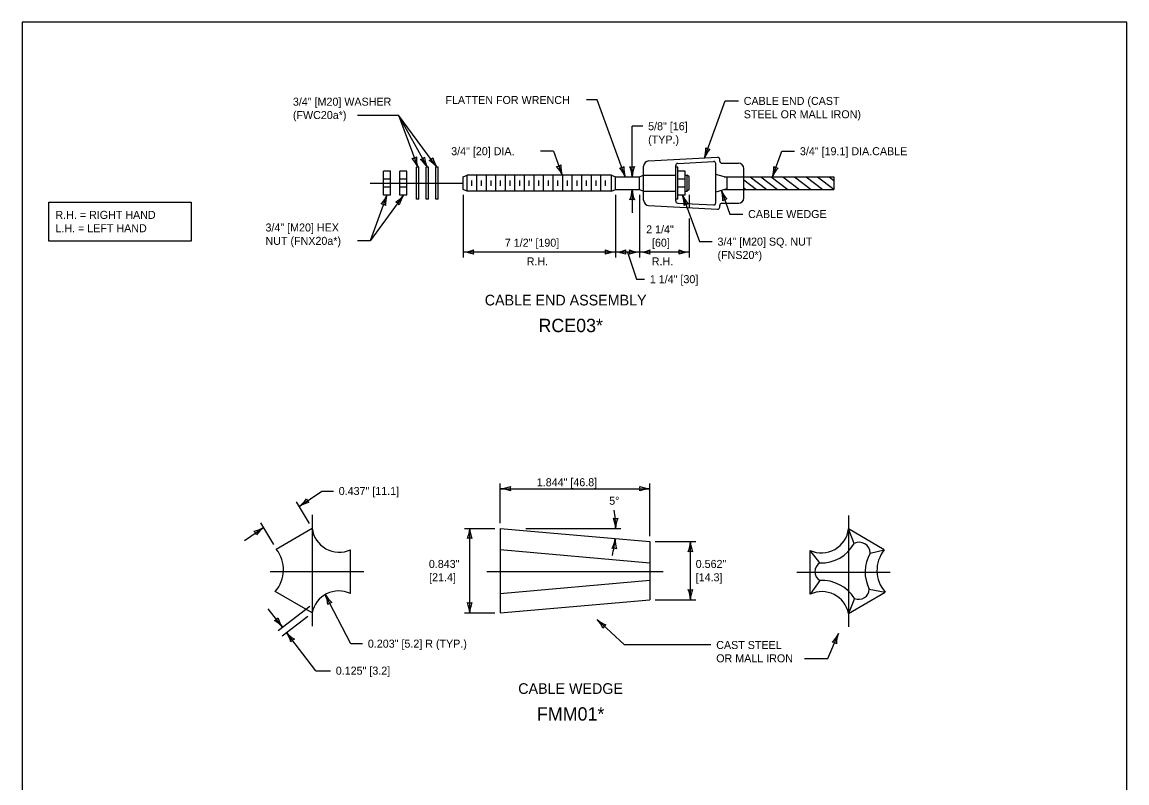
# Model space of a CAD drawing. Extents: x 49991.4 to 50021, y 49987.6 to 50011.4.
# Drawn here: x 50000.34 to 50008.61, y 50005.56 to 50011.26 of the extents above; entities that cross this region are included whole.
import ezdxf

# ---------------------------------------------------------------- set-up
doc = ezdxf.new("R2010")
doc.units = 0
for name, color, linetype in [('Level 1', 7, 'Continuous'), ('Level 2', 7, 'Continuous'), ('Level 3', 7, 'Continuous'), ('Level 4', 7, 'Continuous'), ('Level 5', 7, 'Continuous')]:
    doc.layers.add(name, color=color, linetype=linetype)

msp = doc.modelspace()

# ---------------------------------------------------------------- linework, layer by layer
at = {"layer": 'Level 1'}
for p, q in [((50005.0307, 50010.2226), (50005.5471, 50010.2498)), ((50005.2487, 50010.2041), (50005.5171, 50010.2182)), ((50005.5637, 50010.2215), (50005.5637, 50010.2341)), ((50003.0429, 50009.9656), (50003.0429, 50010.1456)), ((50003.0954, 50010.1456), (50003.0429, 50010.1456)), ((50003.0954, 50009.9656), (50003.0954, 50010.1456)), ((50003.1674, 50009.9656), (50003.1674, 50010.1456)), ((50003.2199, 50010.1456), (50003.1674, 50010.1456)), ((50003.2199, 50009.9656), (50003.2199, 50010.1456)), ((50003.3087, 50010.1756), (50003.2919, 50010.1756)), ((50003.2919, 50009.9356), (50003.2919, 50010.1756)), ((50003.3087, 50009.9356), (50003.3087, 50010.1756)), ((50003.3807, 50010.1756), (50003.3639, 50010.1756)), ((50003.3639, 50009.9356), (50003.3639, 50010.1756)), ((50003.3807, 50009.9356), (50003.3807, 50010.1756)), ((50003.4527, 50010.1756), (50003.4359, 50010.1756)), ((50003.4359, 50009.9356), (50003.4359, 50010.1756)), ((50003.4527, 50009.9356), (50003.4527, 50010.1756)), ((50004.9933, 50009.9279), (50004.9933, 50010.1832)), ((50005.2338, 50009.9228), (50005.2338, 50010.1883)), ((50005.2506, 50010.1756), (50005.2338, 50010.1756)), ((50005.2506, 50009.9356), (50005.2506, 50010.1756)), ((50005.3046, 50010.1456), (50005.2506, 50010.1456)), ((50005.3046, 50009.9656), (50005.3046, 50010.1456)), ((50005.5337, 50009.9087), (50005.5337, 50010.2024)), ((50005.5795, 50010.2057), (50005.7044, 50010.2057)), ((50005.7439, 50009.9449), (50005.7439, 50010.1662)), ((50003.0954, 50010.0856), (50003.0429, 50010.0856)), ((50003.2199, 50010.0856), (50003.1674, 50010.0856)), ((50003.6414, 50010.1036), (50003.6714, 50010.1156)), ((50003.6414, 50010.0075), (50003.6414, 50010.1036)), ((50003.6714, 50009.9956), (50003.6714, 50010.1156)), ((50004.7522, 50010.1156), (50003.6714, 50010.1156)), ((50003.7069, 50010.0369), (50003.7069, 50010.0763)), ((50003.7429, 50009.9956), (50003.7429, 50010.1156)), ((50003.7784, 50010.0369), (50003.7784, 50010.0763)), ((50003.8145, 50009.9956), (50003.8145, 50010.1156)), ((50003.85, 50010.0369), (50003.85, 50010.0763)), ((50003.886, 50009.9956), (50003.886, 50010.1156)), ((50003.9215, 50010.0369), (50003.9215, 50010.0763)), ((50003.9576, 50009.9956), (50003.9576, 50010.1156)), ((50003.9931, 50010.0369), (50003.9931, 50010.0763)), ((50004.0291, 50009.9956), (50004.0291, 50010.1156)), ((50004.0646, 50010.0369), (50004.0646, 50010.0763)), ((50004.1007, 50009.9956), (50004.1007, 50010.1156)), ((50004.1362, 50010.0369), (50004.1362, 50010.0763)), ((50004.1722, 50009.9956), (50004.1722, 50010.1156)), ((50004.2077, 50010.0369), (50004.2077, 50010.0763)), ((50004.2437, 50009.9956), (50004.2437, 50010.1156)), ((50004.2792, 50010.0369), (50004.2792, 50010.0763)), ((50004.3153, 50009.9956), (50004.3153, 50010.1156)), ((50004.3508, 50010.0369), (50004.3508, 50010.0763)), ((50004.3868, 50009.9956), (50004.3868, 50010.1156)), ((50004.4223, 50010.0369), (50004.4223, 50010.0763)), ((50004.4584, 50009.9956), (50004.4584, 50010.1156)), ((50004.4939, 50010.0369), (50004.4939, 50010.0763)), ((50004.5299, 50009.9956), (50004.5299, 50010.1156)), ((50004.5654, 50010.0369), (50004.5654, 50010.0763)), ((50004.6015, 50009.9956), (50004.6015, 50010.1156)), ((50004.637, 50010.0369), (50004.637, 50010.0763)), ((50004.673, 50009.9956), (50004.673, 50010.1156)), ((50004.7085, 50010.0369), (50004.7085, 50010.0763)), ((50004.7522, 50009.9956), (50004.7522, 50010.1156)), ((50004.7522, 50010.1156), (50004.7822, 50010.1036)), ((50004.7822, 50010.1036), (50004.9633, 50010.1036)), ((50004.7822, 50010.0075), (50004.7822, 50010.1036)), ((50004.9633, 50010.1036), (50004.9933, 50010.1156)), ((50004.9633, 50010.0075), (50004.9633, 50010.1036)), ((50005.3046, 50010.0856), (50005.2506, 50010.0856)), ((50005.3046, 50010.1156), (50005.3196, 50010.1156)), ((50005.3196, 50009.9956), (50005.3196, 50010.1156)), ((50005.3346, 50010.1036), (50005.3196, 50010.1156)), ((50005.3346, 50010.0075), (50005.3346, 50010.1036)), ((50005.7439, 50010.1033), (50006.418, 50010.1033)), ((50005.7439, 50010.0803), (50005.8386, 50010.0079)), ((50005.792, 50010.1033), (50005.9172, 50010.0079)), ((50005.871, 50010.1033), (50005.996, 50010.0079)), ((50005.9492, 50010.1033), (50006.0744, 50010.0079)), ((50006.0364, 50010.1033), (50006.1614, 50010.0079)), ((50006.1242, 50010.1033), (50006.2492, 50010.0079)), ((50006.212, 50010.1033), (50006.3372, 50010.0079)), ((50006.2972, 50010.1033), (50006.418, 50010.0111)), ((50006.3824, 50010.1033), (50006.418, 50010.0761)), ((50006.418, 50010.1033), (50006.418, 50010.0079)), ((50003.0954, 50010.0256), (50003.0429, 50010.0256)), ((50003.0954, 50009.9656), (50003.0429, 50009.9656)), ((50003.2199, 50010.0256), (50003.1674, 50010.0256)), ((50003.2199, 50009.9656), (50003.1674, 50009.9656)), ((50003.6714, 50009.9956), (50003.6414, 50010.0075)), ((50004.7522, 50009.9956), (50003.6714, 50009.9956)), ((50004.7522, 50009.9956), (50004.7822, 50010.0075)), ((50004.7822, 50010.0075), (50004.9633, 50010.0075)), ((50004.9633, 50010.0075), (50004.9933, 50009.9956)), ((50005.3046, 50010.0256), (50005.2506, 50010.0256)), ((50005.3046, 50009.9656), (50005.2506, 50009.9656)), ((50005.3046, 50009.9956), (50005.3196, 50009.9956)), ((50005.3346, 50010.0075), (50005.3196, 50009.9956)), ((50005.7439, 50010.0201), (50005.7598, 50010.0079)), ((50005.7439, 50010.0079), (50006.418, 50010.0079)), ((50003.3087, 50009.9356), (50003.2919, 50009.9356)), ((50003.3807, 50009.9356), (50003.3639, 50009.9356)), ((50003.4527, 50009.9356), (50003.4359, 50009.9356)), ((50005.0307, 50009.8885), (50005.5471, 50009.8613)), ((50005.2506, 50009.9356), (50005.2338, 50009.9356)), ((50005.2487, 50009.9071), (50005.5171, 50009.8929)), ((50005.5637, 50009.8771), (50005.5637, 50009.8897)), ((50005.5795, 50009.9055), (50005.7044, 50009.9055)), ((50002.2405, 50007.3134), (50002.5087, 50007.4706)), ((50003.9192, 50007.4693), (50003.9192, 50006.837)), ((50003.9192, 50007.4693), (50005.0398, 50007.371)), ((50006.7963, 50007.3089), (50006.5287, 50007.4657)), ((50006.5707, 50007.3562), (50006.5287, 50007.4657)), ((50005.0398, 50007.371), (50005.0398, 50006.9353)), ((50002.7963, 50006.9811), (50002.7963, 50007.3089)), ((50003.9192, 50007.3105), (50005.0398, 50007.2123)), ((50006.2413, 50006.9763), (50006.2413, 50007.3041)), ((50006.3129, 50007.211), (50006.2413, 50007.3041)), ((50006.6913, 50007.2843), (50006.7963, 50007.3089)), ((50003.9192, 50006.9828), (50005.0398, 50007.0811)), ((50006.3129, 50007.079), (50006.2413, 50006.9763)), ((50002.5089, 50006.837), (50002.2327, 50006.9967)), ((50006.5285, 50006.8322), (50006.8035, 50006.9912)), ((50006.6844, 50007.0137), (50006.8035, 50006.9912)), ((50003.9192, 50006.837), (50005.0398, 50006.9353)), ((50006.5739, 50006.9451), (50006.5285, 50006.8322))]:
    msp.add_line(p, q, dxfattribs=at)
msp.add_lwpolyline([(50008.6146, 50011.2628), (50000.3356, 50011.2628), (50000.3356, 50000.0624), (50008.6146, 50000.0624)], close=True, dxfattribs=at)
for centre, radius, start, end in [((50005.0328, 50010.1832), 0.0395, 93.01385, 180), ((50005.5179, 50010.2024), 0.0158, 0, 93.01385), ((50005.548, 50010.2341), 0.0158, 0, 93.01385), ((50005.5795, 50010.2215), 0.0158, 180, 270), ((50005.2495, 50010.1883), 0.0158, 93.01385, 180), ((50005.7044, 50010.1662), 0.0395, 0, 90), ((50005.0328, 50009.9279), 0.0395, 180, 266.98615), ((50005.2495, 50009.9228), 0.0158, 180, 266.98615), ((50005.5179, 50009.9087), 0.0158, 266.98615, 0), ((50005.5795, 50009.8897), 0.0158, 90, 180), ((50005.7044, 50009.9449), 0.0395, 270, 0), ((50005.548, 50009.8771), 0.0158, 266.98615, 360), ((50002.7118, 50007.4953), 0.2046, 186.9475, 294.37019), ((50006.3257, 50007.4905), 0.2045, 245.63563, 353.05167), ((50002.0486, 50007.1597), 0.2459, 318.4943, 38.69231), ((50006.3253, 50007.4905), 0.2797, 267.46243, 331.31637), ((50006.608, 50007.2818), 0.0833, 1.76722, 116.65123), ((50006.9322, 50007.1428), 0.2794, 149.56584, 207.51965), ((50006.987, 50007.1543), 0.2455, 140.9689, 221.62763), ((50006.3551, 50007.145), 0.0784, 122.61957, 237.40196), ((50006.3299, 50006.7908), 0.2887, 32.3072, 93.37678), ((50002.7091, 50006.7964), 0.2043, 64.74095, 168.51786), ((50006.3284, 50006.7917), 0.2042, 11.45742, 115.25299), ((50006.6053, 50007.0178), 0.0792, 246.64352, 357.03121)]:
    msp.add_arc(centre, radius, start, end, dxfattribs=at)
at = {"layer": 'Level 2'}
for p, q in [((50004.8505, 50006.5959), (50004.6438, 50006.7866)), ((50006.3728, 50006.4959), (50006.4526, 50006.6809)), ((50005.4972, 50006.5959), (50004.8505, 50006.5959)), ((50006.1978, 50006.4959), (50006.3728, 50006.4959))]:
    msp.add_line(p, q, dxfattribs=at)
msp.add_lwpolyline([(50000.5358, 50009.914), (50001.6023, 50009.914), (50001.6023, 50009.6225), (50000.5358, 50009.6225)], close=True, dxfattribs=at)
at = {"layer": 'Level 3'}
for p, q in [((50004.6446, 50010.6793), (50004.5646, 50010.6793)), ((50004.8555, 50010.1036), (50004.6446, 50010.6793)), ((50005.4481, 50010.2446), (50005.6047, 50010.6722)), ((50005.6047, 50010.6722), (50005.7033, 50010.6722)), ((50002.8479, 50010.5664), (50003.1571, 50010.5664)), ((50003.1571, 50010.5664), (50003.3003, 50010.1756)), ((50003.3723, 50010.1756), (50003.1571, 50010.5664)), ((50003.4443, 50010.1756), (50003.1571, 50010.5664)), ((50004.9868, 50010.4826), (50004.9068, 50010.4826)), ((50004.9068, 50010.1036), (50004.9068, 50010.4826)), ((50004.3168, 50010.2955), (50004.2208, 50010.2955)), ((50004.3168, 50010.2955), (50004.3827, 50010.1156)), ((50005.9581, 50010.1033), (50006.0285, 50010.2954)), ((50006.0285, 50010.2954), (50006.1245, 50010.2954)), ((50003.0691, 50009.9656), (50002.9439, 50009.6239)), ((50003.1936, 50009.9656), (50002.9439, 50009.6239)), ((50003.6414, 50009.9675), (50003.6414, 50009.4999)), ((50004.7822, 50009.9675), (50004.7822, 50009.4999)), ((50004.9068, 50010.0075), (50004.9068, 50009.8341)), ((50004.9633, 50009.9675), (50004.9633, 50009.4999)), ((50005.2855, 50009.9656), (50005.4128, 50009.6181)), ((50005.3346, 50009.9675), (50005.3346, 50009.8718)), ((50005.5757, 50010.0016), (50005.6401, 50009.8247)), ((50005.6401, 50009.8247), (50005.7361, 50009.8247)), ((50005.3346, 50009.7918), (50005.3346, 50009.4999)), ((50002.9439, 50009.6239), (50002.8479, 50009.6239)), ((50005.4128, 50009.6181), (50005.5068, 50009.6181)), ((50005.3346, 50009.5399), (50003.6414, 50009.5399)), ((50002.4127, 50007.6337), (50002.5821, 50007.7493)), ((50002.5821, 50007.7493), (50002.6683, 50007.7493)), ((50003.9192, 50007.5093), (50003.9192, 50007.807)), ((50003.9192, 50007.767), (50005.0398, 50007.767)), ((50005.0398, 50007.411), (50005.0398, 50007.807)), ((50002.4882, 50007.5049), (50002.3925, 50007.6682)), ((50002.221, 50007.3483), (50002.1253, 50007.5117)), ((50002.0023, 50007.3795), (50002.1455, 50007.4772)), ((50003.6496, 50007.4693), (50003.8792, 50007.4693)), ((50003.6896, 50006.837), (50003.6896, 50007.4693)), ((50004.1112, 50007.4693), (50004.8229, 50007.4693)), ((50005.0798, 50007.371), (50005.3834, 50007.371)), ((50005.3434, 50006.9353), (50005.3434, 50007.371)), ((50002.7991, 50006.6057), (50002.6073, 50006.9735)), ((50005.0798, 50006.9353), (50005.3834, 50006.9353)), ((50002.2862, 50006.7291), (50002.1804, 50006.8665)), ((50002.2545, 50006.7048), (50002.4919, 50006.8871)), ((50003.6496, 50006.837), (50003.8792, 50006.837)), ((50002.2849, 50006.665), (50002.4772, 50006.8127)), ((50002.5363, 50006.4034), (50002.3166, 50006.6894)), ((50002.8867, 50006.6057), (50002.7991, 50006.6057)), ((50002.5363, 50006.4034), (50002.6463, 50006.4034))]:
    msp.add_line(p, q, dxfattribs=at)
msp.add_lwpolyline([(50004.8728, 50009.5399), (50004.94, 50009.3367), (50004.9997, 50009.3367)], dxfattribs=at)
for centre, radius, start, end in [((50005.2256, 50010.3139), 0.233, 342.70268, 1.95253), ((50005.6535, 50010.1596), 0.2223, 137.33138, 157.51489), ((50005.4922, 50010.365), 0.0548, 232.01419, 267.73655), ((50003.2562, 50010.296), 0.0548, 272.26345, 307.98581), ((50003.0857, 50010.0847), 0.233, 22.95194, 42.20179), ((50003.512, 50010.2434), 0.2223, 177.58064, 197.76415), ((50003.3104, 50010.2879), 0.0548, 280.97926, 316.70162), ((50003.174, 50010.0532), 0.233, 31.66775, 50.9176), ((50003.5713, 50010.2747), 0.2223, 186.29645, 206.47996), ((50003.3683, 50010.2789), 0.0548, 288.45146, 324.17382), ((50003.2636, 50010.0285), 0.233, 39.13995, 58.3898), ((50003.6287, 50010.2997), 0.2223, 193.76865, 213.95216), ((50004.3386, 50010.236), 0.0548, 272.26345, 307.98581), ((50004.1681, 50010.0247), 0.233, 22.95194, 42.20179), ((50004.5944, 50010.1834), 0.2223, 177.58064, 197.76415), ((50004.8114, 50010.224), 0.0548, 272.26345, 307.98581), ((50004.6501, 50010.0186), 0.2223, 22.48511, 42.66862), ((50005.078, 50010.1729), 0.233, 178.04747, 197.29732), ((50004.6847, 50010.0944), 0.2223, 2.36048, 22.54399), ((50004.9068, 50010.2318), 0.0548, 252.13882, 287.86118), ((50005.1395, 50010.0921), 0.233, 157.92284, 177.17269), ((50005.7357, 50010.1726), 0.233, 342.70268, 1.95253), ((50006.1636, 50010.0183), 0.2223, 137.33138, 157.51489), ((50006.0022, 50010.2237), 0.0548, 232.01419, 267.73655), ((50002.8637, 50010.0506), 0.2223, 317.33138, 337.51489), ((50003.2916, 50009.8963), 0.233, 162.70268, 181.95253), ((50003.0197, 50010.104), 0.2223, 301.29634, 321.47985), ((50003.3883, 50009.8375), 0.233, 146.66764, 165.91749), ((50004.6847, 50010.0167), 0.2223, 337.45601, 357.63952), ((50005.1395, 50010.019), 0.233, 182.82731, 202.07716), ((50005.0738, 50009.8977), 0.2223, 357.58064, 17.76415), ((50005.5001, 50010.0564), 0.233, 202.95194, 222.20179), ((50005.364, 50009.9337), 0.2223, 357.58064, 17.76415), ((50005.7903, 50010.0924), 0.233, 202.95194, 222.20179), ((50003.025, 50009.8452), 0.0548, 52.01419, 87.73655), ((50003.118, 50009.8621), 0.0548, 35.97915, 71.70151), ((50004.9068, 50009.8793), 0.0548, 72.13882, 107.86118), ((50005.3296, 50009.8452), 0.0548, 92.26345, 127.98581), ((50005.6198, 50009.8812), 0.0548, 92.26345, 127.98581), ((50003.6299, 50009.7726), 0.233, 272.82731, 292.07716), ((50003.7696, 50009.5399), 0.0548, 162.13882, 197.86118), ((50004.7914, 50009.762), 0.2223, 247.45601, 267.63952), ((50004.654, 50009.5399), 0.0548, 342.13882, 17.86118), ((50004.7707, 50009.7726), 0.233, 272.82731, 292.07716), ((50004.9104, 50009.5399), 0.0548, 162.13882, 197.86118), ((50004.9725, 50009.762), 0.2223, 247.45601, 267.63952), ((50004.8351, 50009.5399), 0.0548, 342.13882, 17.86118), ((50004.9518, 50009.7726), 0.233, 272.82731, 292.07716), ((50005.0915, 50009.5399), 0.0548, 162.13882, 197.86118), ((50005.3437, 50009.762), 0.2223, 247.45601, 267.63952), ((50005.2063, 50009.5399), 0.0548, 342.13882, 17.86118), ((50003.6322, 50009.3178), 0.2223, 67.45601, 87.63952), ((50004.7937, 50009.3072), 0.233, 92.82731, 112.07716), ((50004.7731, 50009.3178), 0.2223, 67.45601, 87.63952), ((50004.9748, 50009.3072), 0.233, 92.82731, 112.07716), ((50004.9542, 50009.3178), 0.2223, 67.45601, 87.63952), ((50005.3461, 50009.3072), 0.233, 92.82731, 112.07716), ((50003.9077, 50007.9998), 0.233, 272.82731, 292.07716), ((50003.9101, 50007.5449), 0.2223, 67.45601, 87.63952), ((50004.0474, 50007.767), 0.0548, 162.13882, 197.86118), ((50005.049, 50007.9892), 0.2223, 247.45601, 267.63952), ((50004.9116, 50007.767), 0.0548, 342.13882, 17.86118), ((50005.0513, 50007.5343), 0.233, 92.82731, 112.07716), ((50002.272, 50007.8194), 0.233, 307.13727, 326.38712), ((50002.5304, 50007.445), 0.2223, 101.76597, 121.94948), ((50002.5186, 50007.7059), 0.0548, 196.44878, 232.17114), ((50003.9193, 50007.4693), 0.8637, 0.00525, 9.13696), ((50004.7829, 50007.5976), 0.0548, 252.13882, 287.86118), ((50004.5502, 50007.4578), 0.233, 2.82731, 22.07716), ((50005.0051, 50007.4602), 0.2223, 157.45601, 177.63952), ((50002.0279, 50007.6658), 0.2223, 281.76589, 301.94939), ((50002.0396, 50007.4049), 0.0548, 16.44869, 52.17106), ((50002.2862, 50007.2915), 0.233, 127.13719, 146.38704), ((50003.4675, 50007.4785), 0.2223, 337.45601, 357.63952), ((50003.6896, 50007.3411), 0.0548, 72.13882, 107.86118), ((50003.9223, 50007.4808), 0.233, 182.82731, 202.07716), ((50004.5592, 50007.4224), 0.2223, 332.44311, 352.62662), ((50004.7684, 50007.2661), 0.0548, 67.12592, 102.84828), ((50003.9193, 50007.4693), 0.8637, 346.45769, 354.9871), ((50005.0125, 50007.385), 0.233, 177.81441, 197.06426), ((50005.1213, 50007.3802), 0.2223, 337.45601, 357.63952), ((50005.5761, 50007.3825), 0.233, 182.82731, 202.07716), ((50005.3434, 50007.2428), 0.0548, 72.13882, 107.86118), ((50005.3434, 50007.0636), 0.0548, 252.13882, 287.86118), ((50005.1107, 50006.9238), 0.233, 2.82731, 22.07716), ((50005.5656, 50006.9262), 0.2223, 157.45601, 177.63952), ((50002.4061, 50006.8789), 0.2223, 4.99492, 25.17843), ((50002.8084, 50007.0913), 0.233, 210.36622, 229.61607), ((50002.6666, 50006.8598), 0.0548, 99.67773, 135.40009), ((50003.6896, 50006.9653), 0.0548, 252.13882, 287.86118), ((50003.4569, 50006.8255), 0.233, 2.82731, 22.07716), ((50003.9118, 50006.8279), 0.2223, 157.45601, 177.63952), ((50002.2079, 50006.8307), 0.0548, 289.75234, 325.4747), ((50002.1089, 50006.578), 0.233, 40.44083, 59.69068), ((50002.4678, 50006.8575), 0.2223, 195.06953, 215.25304), ((50004.4865, 50006.6295), 0.2223, 24.77495, 44.95846), ((50004.7931, 50006.9654), 0.233, 230.14625, 249.3961), ((50004.738, 50006.6997), 0.0548, 119.45776, 155.18012), ((50002.1349, 50006.5614), 0.2223, 14.9839, 35.16741), ((50002.4942, 50006.8403), 0.233, 220.3552, 239.60505), ((50006.2523, 50006.7773), 0.2223, 314.12459, 334.3081), ((50006.6709, 50006.5993), 0.233, 159.49589, 178.74574), ((50002.3947, 50006.5877), 0.0548, 109.66671, 145.38907), ((50006.4018, 50006.5632), 0.0548, 48.8074, 84.52976)]:
    msp.add_arc(centre, radius, start, end, dxfattribs=at)
at = {"layer": 'Level 4'}
for p, q in [((50004.9933, 50010.1156), (50005.2338, 50010.1156)), ((50005.6177, 50010.0976), (50005.5337, 50010.1216)), ((50005.5976, 50010.1033), (50005.7439, 50010.1033)), ((50005.6177, 50010.0976), (50005.6177, 50010.0136)), ((50004.9933, 50009.9956), (50005.2338, 50009.9956)), ((50005.6177, 50010.0136), (50005.5337, 50009.9896)), ((50005.5979, 50010.0079), (50005.7439, 50010.0079))]:
    msp.add_line(p, q, dxfattribs=at)
at = {"layer": 'Level 5'}
for p, q in [((50002.9429, 50010.0556), (50003.6414, 50010.0556)), ((50002.5087, 50007.5706), (50002.5087, 50006.7372)), ((50006.5287, 50007.5657), (50006.5287, 50006.7324)), ((50002.1941, 50007.146), (50002.8963, 50007.146)), ((50003.8192, 50007.146), (50005.1398, 50007.146)), ((50006.1413, 50007.1412), (50006.8418, 50007.1412))]:
    msp.add_line(p, q, dxfattribs=at)

# ---------------------------------------------------------------- texts
at = {"layer": 'Level 2'}
for s, height, p in [('FLATTEN FOR WRENCH', 0.06, (50003.5079, 50010.6493)), ('3/4" [M20] WASHER', 0.06, (50002.365, 50010.6364)), ('CABLE END (CAST', 0.06, (50005.7433, 50010.6422)), ('(FWC20a*)', 0.06, (50002.365, 50010.5364)), ('STEEL OR MALL IRON)', 0.06, (50005.7433, 50010.5422)), ('5/8" [16]', 0.06, (50005.0268, 50010.4526)), ('(TYP.)', 0.06, (50005.0268, 50010.3526)), ('3/4" [20] DIA.', 0.06, (50003.5512, 50010.2655)), ('3/4" [19.1] DIA.CABLE', 0.06, (50006.1645, 50010.2654)), ('R.H. = RIGHT HAND', 0.06, (50000.5854, 50009.7883)), ('CABLE WEDGE', 0.06, (50005.7761, 50009.7947)), ('L.H. = LEFT HAND', 0.06, (50000.5854, 50009.6883)), ('3/4" [M20] HEX', 0.06, (50002.1595, 50009.6939)), ('2 1/4"', 0.06, (50005.012, 50009.6799)), ('NUT (FNX20a*)', 0.06, (50002.1595, 50009.5939)), ('7 1/2" [190]', 0.06, (50003.9531, 50009.5799)), ('[60]', 0.06, (50005.0558, 50009.5799)), ('3/4" [M20] SQ. NUT', 0.06, (50005.5468, 50009.5881)), ('(FNS20*)', 0.06, (50005.5468, 50009.4881)), ('R.H.', 0.06, (50004.117, 50009.4399)), ('R.H.', 0.06, (50005.0542, 50009.4399)), ('1 1/4" [30]', 0.06, (50005.0397, 50009.3067)), ('CABLE END ASSEMBLY', 0.08, (50003.8025, 50009.1399)), ('RCE03*', 0.1, (50004.2052, 50008.9399)), ('1.844" [46.8]', 0.06, (50004.1926, 50007.7853)), ('0.437" [11.1]', 0.06, (50002.7083, 50007.7194)), ('5°', 0.06, (50004.7349, 50007.6464)), ('0.843"', 0.06, (50003.3837, 50007.1732)), ('0.562"', 0.06, (50005.3834, 50007.1732)), ('[21.4]', 0.06, (50003.3856, 50007.0732)), ('[14.3]', 0.06, (50005.3834, 50007.0732)), ('0.203" [5.2] R (TYP.)', 0.06, (50002.9267, 50006.5759)), ('CAST STEEL', 0.06, (50005.5372, 50006.5659)), ('OR MALL IRON', 0.06, (50005.5372, 50006.4659)), ('0.125" [3.2]', 0.06, (50002.6863, 50006.3735)), ('CABLE WEDGE', 0.08, (50004.0536, 50006.2294)), ('FMM01*', 0.1, (50004.1938, 50006.0294))]:
    msp.add_text(s, height=height, dxfattribs=at).set_placement(p)

doc.saveas('drawing.dxf')
